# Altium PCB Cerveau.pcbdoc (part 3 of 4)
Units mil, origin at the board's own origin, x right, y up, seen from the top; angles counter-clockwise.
Board outline 3985.6 x 3546.5 mil, 2 copper layers (Top Layer, Bottom Layer), stack 62.2 mil thick; 170 components, 173 nets, 734 pads, 576 vias.
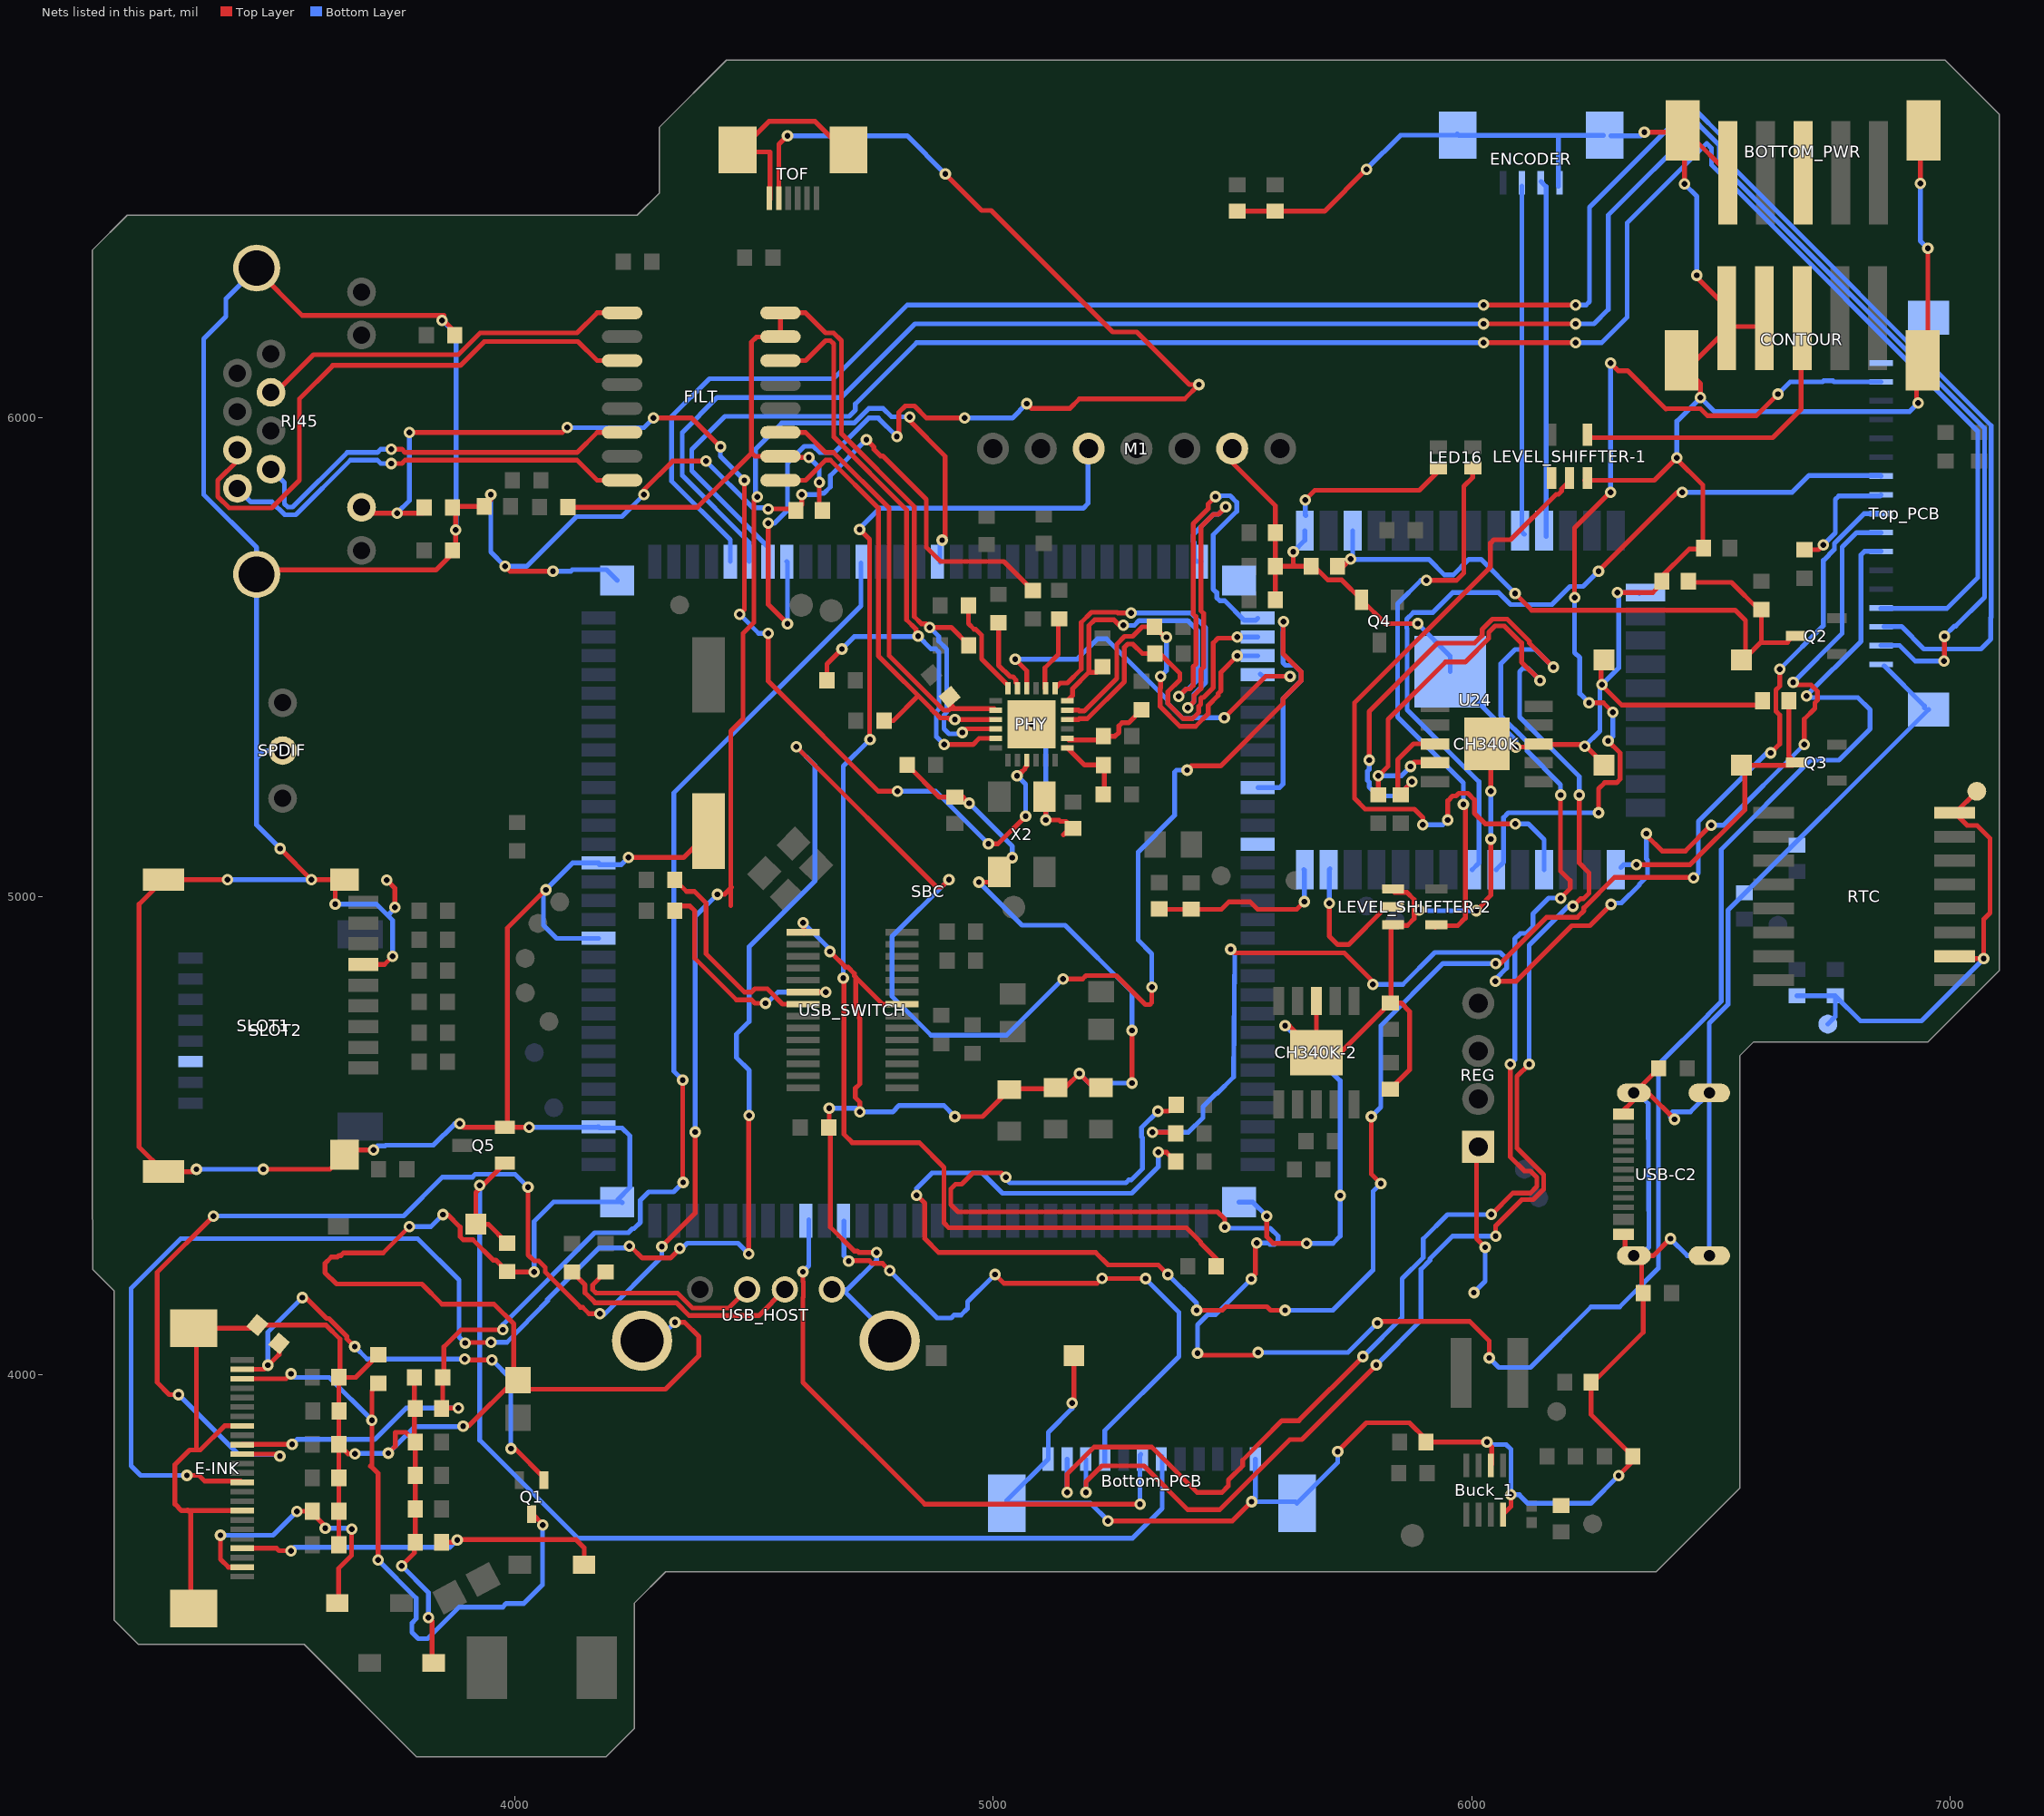
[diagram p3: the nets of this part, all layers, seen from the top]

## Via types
v1: diameter 24, hole 12, Top Layer to Bottom Layer, 576 vias

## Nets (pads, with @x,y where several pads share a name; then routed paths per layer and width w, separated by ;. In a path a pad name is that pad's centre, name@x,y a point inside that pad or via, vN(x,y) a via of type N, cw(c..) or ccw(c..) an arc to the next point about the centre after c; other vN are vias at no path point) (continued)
E-INK_D/C: E-INK.11 SBC.16 | length 4549
  Top Layer w10: v1(3297.7,3958.8) 3278.3,3958.8 3253,3984.2 3253,4214.4 v1(3370.7,4332.1) ; E-INK.11@3430.7,3834.5 3505.1,3834.5 v1(3509.3,3830.3) ; v1(4027.9,4392.5) 4027.9,4251 4040.6,4238.3 4050.2,4238.3 4063.7,4224.8 4063.7,4215.1 4137.6,4141.2 4142,4141.2 4155.3,4127.9 v1(4178.3,4127.9) ; v1(4307.4,4268.6) 4377,4338.2 v1(4377,4507.8) ; v1(4423.7,5004.5) 4438.6,5004.5 4451.5,5017.4 ; 4451.5,4980.7 4451.5,5017.4 ; 4453.5,5019.4 4451.5,5017.4 ; v1(4507.2,5835.3) 4500,5828.1 4500,5572.6 4477.3,5549.9 4477.3,5371.1 4451.5,5345.3 4451.5,5017.4 ; v1(4825.8,6002.4) 4825.8,5993.9 4899.4,5920.3 4899.4,5751 v1(4893.2,5744.8)
  Bottom Layer w10: v1(3297.7,3958.8) 3422.8,3833.7 v1@3509.9,3833.7 ; v1(3370.7,4332.1) 3767.8,4332.1 3849,4413.4 3911.5,4413.4 3917.5,4419.4 4000.9,4419.4 v1(4027.9,4392.5) ; v1@4180.2,4126.9 4187.5,4126.9 4307.7,4247.2 v1@4307.7,4267.1 ; v1(4377,4507.8) 4377,4957.8 v1(4423.7,5004.5) ; v1(4507.2,5835.3) 4503.1,5839.4 4503.1,5934.4 4558.3,5989.6 4709.6,5989.6 4740,6020 4770,6020 4787.6,6002.4 v1(4825.8,6002.4) ; SBC.16@4888.4,5699 4888.4,5740 v1(4893.2,5744.8)
E-INK_DIN: E-INK.14 SBC.40 | length 6237.3
  Top Layer w10: v1(3315,3790) 3340.2,3790 3351.9,3778.3 3427.9,3778.3 E-INK.14@3430.7,3775.5 ; v1(3896.4,4066.7) 3897.3,4067.6 v1@3948.2,4067.6 ; v1(4239.6,4269.3) 4241.7,4269.3 4266.6,4244.4 4325.3,4244.4 v1(4345.2,4264.3) ; v1(4489.2,4253) 4489.2,4541.5 v1(4490.1,4542.4) ; v1(4588.6,5312.9) 4881.9,5019.6 4891.9,5019.6 v1(4907.5,5035.1) ; v1(5145.8,4827.7) 5186.8,4827.7 5193.8,4834.7 5257.1,4834.7 5317.9,4774 5327.3,4774 5331.5,4778.2 v1(5331.5,4810.5) ; v1(5405.1,5264) 5414.1,5272.9 5475.3,5272.9 5605.5,5403.1 5605.5,5412.7 5643.5,5450.7 5643.5,5469.7 5605.5,5507.7 5605.5,5551.6 5606.4,5552.6 v1(5606.4,5574.6)
  Bottom Layer w10: v1@3316.2,3789.9 3218.6,3789.9 3198.3,3810.2 3198.3,4181.1 3302.1,4284.9 3797,4284.9 3883.6,4198.3 3883.6,4079.5 v1(3896.4,4066.7) ; v1(3950.8,4068.2) 3983.7,4068.2 4068.9,4154.9 ; 4068.4,4155.3 4068.4,4157.7 4177,4265.6 4240.6,4265.6 v1@4245.2,4270.3 ; v1(4345.2,4264.3) 4349.1,4264.3 4360.5,4275.6 4466.6,4275.6 v1(4489.2,4253) ; v1(4490.1,4542.4) 4490.1,4636.5 4463.5,4663.1 4463.5,4712.2 4490.1,4738.7 4490.1,4895.1 4627.2,5032.2 4627.2,5274.3 v1(4588.6,5312.9) ; v1(4907.5,5035.1) 4788.4,4916 4788.4,4791.6 4870,4710 5028.1,4710 v1(5145.8,4827.7) ; v1(5331.5,4810.5) 5331.5,4880.3 5302.7,4909.1 5302.7,5092.9 5379,5169.2 5379,5259.9 5383.1,5264 v1(5405.1,5264) ; SBC.40@5553,5227.6 5598.4,5227.6 5605.5,5234.6 5605.5,5412.7 5643.5,5450.7 5643.5,5469.7 5630,5483.2 5610.9,5483.2 5605.5,5488.7 5605.5,5573.6 v1(5606.4,5574.6)
E-INK_GDR: E-INK.2 Q1.1 R28.2 | length 1034.8
  Top Layer w10: E-INK.2@3430.7,4011.7 3476.7,4011.7 3507.7,4042.7 R28.2@3507.7,4065.9 ; v1(3556.2,4161.7) 3563.2,4161.7 3606.8,4118.1 3611.7,4118.1 3649,4080.8 3649,4075.9 v1(3665.7,4059.2) ; v1(3895.3,4033.2) 3897,4031.4 v1(3952.7,4031.4) ; v1(3992,3846) 4000.8,3846 Q1.1@4062.2,3784.6
  Bottom Layer w10: v1(3484.2,4020.4) 3484.2,4089.7 v1(3556.2,4161.7) ; v1(3665.7,4059.2) 3691.7,4033.2 v1(3895.3,4033.2) ; v1(3952.7,4031.4) 3992,3992.1 v1(3992,3846)
E-INK_PREGL: C24.1 E-INK.23 U23.2 | length 563.6
  Top Layer w10: v1(3385,3665) 3385,3615 3401.7,3598.3 E-INK.23@3430.7,3598.3 ; v1(3545,3715) C24.1@3577.4,3715 ; C24.1@3586,3702.1 3604.2,3683.9 v1(3604.2,3679.4) ; U23.2@3632.1,3527.9 3632.1,3595.6 3659.3,3622.7 3659.3,3677.7 v1(3659.7,3678)
  Bottom Layer w10: v1(3385,3665) 3495,3665 v1(3545,3715) ; v1(3604.2,3679.4) 3658.3,3679.4 v1(3659.7,3678)
E-INK_PREVGH: C22.1 E-INK.21 U21.1 | length 798.4
  Top Layer w10: E-INK.21@3430.7,3637.7 3502.3,3637.7 3507.5,3632.5 v1(3532.5,3632.5) ; C22.1@3847.6,3650 3875,3650 v1(3880,3655) ; v1@3883.8,3655.7 4128.5,3655.7 4145.6,3638.7 4145.6,3605.1 U21.1@4145.1,3604.6
  Bottom Layer w10: v1(3532.5,3632.5) 3540,3640 3865,3640 v1(3880,3655)
E-INK_RESE: E-INK.3 Q1.3 R27.1 | length 1367.7
  Top Layer w10: E-INK.3@3430.7,3992 3522,3992 v1(3532.5,4002.5) ; 3697.8,3809.2 3700,3811.4 ; 3699.6,3809.2 3714.7,3794.1 v1(3714.7,3613) ; 3701.6,3811.4 v1(3701.6,3905.5) 3701.6,3966.9 R27.1@3715,3980.3 ; Q1.3@4035.2,3711.3 4058.4,3688.1 v1(4058.4,3686.5)
  Bottom Layer w10: v1(3532.5,4002.5) 3540,3995 3612.1,3995 v1(3701.6,3905.5) ; v1(3714.7,3613) 3794.2,3533.4 3794.2,3490.3 3785.3,3481.3 3785.3,3462.3 3798.7,3448.8 3817.8,3448.8 3883.6,3514.6 3975,3514.6 3982.7,3522.4 4019.5,3522.4 4058.4,3561.3 v1(4058.4,3686.5)
E-INK_RST: C15.2 E-INK.10 R54.2 SBC.12 | length 2793.2
  Top Layer w10: E-INK.10@3430.7,3854.2 3431.5,3855 v1(3535,3855) ; C15.2@3847.6,3930 C15.2@3848.6,3931 ; R54.2@3849.7,3995 3849.7,3932.1 C15.2@3848.6,3931 ; R54.2@3852.7,3991.8 3852.1,3992.5 3852.1,4058.6 3888,4094.5 v1(3975.3,4094.5) ; v1(3882.6,3931) C15.2@3848.6,3931 ; v1@4350,4400.1 4351.2,4401.4 v1(4351.2,4616.4)
  Bottom Layer w10: v1(3535,3855) 3545.2,3865.2 3707.3,3865.2 3772.8,3930.7 v1@3882.6,3930.7 ; v1(3975.3,4094.5) 3975.3,4105.1 4167.3,4297.1 4237.6,4297.1 4246.1,4305.6 4249.3,4305.6 4262.7,4319 4262.7,4365.4 4279.9,4382.6 4332.2,4382.6 v1(4352.1,4402.4) ; v1(4351.2,4616.4) 4332.7,4634.9 4332.7,5216.4 4723.5,5607.3 SBC.12@4723.5,5697.1
EN_1: C12.1 C13.1 ESP_RST.1 Q2.3 R21.1 U24.3 | length 1438.5
  Top Layer w10: C12.1@5719.8,5690.3 5732.2,5690.3 v1(5747.2,5705.3) ; v1(6090.5,5633.3) 6125.3,5598.5 6550.5,5598.5 6572.1,5576.9 ESP_RST.1@6572.1,5498.7 ; C13.1@6457.8,5656.5 6542.8,5656.5 R21.1@6601.1,5598.2 ; ESP_RST.1@6572.1,5492 ESP_RST.1@6572.1,5498.7 ; R21.1@6604.5,5598.2 R21.1@6605.2,5598.2 ; R21.1@6605.2,5601 R21.1@6605.2,5598.2 ; 6659,5531.4 Q2.3@6672.7,5545.1 ; 6660,5530.3 6603.8,5530.3 ; ESP_RST.1@6572.1,5498.7 6603.8,5530.3 ; 6603.8,5530.3 6605.2,5531.7 R21.1@6605.2,5598.2
  Bottom Layer w10: v1@5747,5704.6 5910.4,5704.6 5942.7,5672.3 5961.8,5672.3 5994,5704.6 6019.2,5704.6 v1(6090.5,5633.3) ; v1@5751.1,5709.2 U24.3@5751.1,5764.6
ENC_A: ENCODER.3 U24.11 | length 746.6
  Bottom Layer w10: ENCODER.3@6144.6,6494.4 6155.5,6483.5 U24.11@6155.5,5752.3
ENC_B: ENCODER.2 U24.10 | length 729.4
  Bottom Layer w10: ENCODER.2@6104.8,6484.5 6104.8,5762.2 U24.10@6109.8,5757.2
ETH_ACT: PHY.3 R26.1 RJ45.11 | length 2399.2
  Top Layer w10: RJ45.11@3686.9,5801.4 v1(3754.1,5801.4) 3806.7,5801.4 R26.1@3817.7,5812.4 ; v1(3780,5970) 4100,5970 v1(4110,5980) ; v1(4290,6000) 4370,6000 v1(4430,5940) ; v1(4470,5590) 4480,5600 v1(4480,5870) ; v1(4530,5550) 4530,5450 4760,5220 v1(4800,5220) ; v1(4990,5110) 5010,5110 v1(5067.7,5167.7) ; v1(5049.7,5252.4) 5058.1,5260.8 5060.5,5260.8 5067,5267.3 5067,5269.7 5070.2,5272.9 PHY.3@5070.2,5284.9
  Bottom Layer w10: v1(3754.1,5801.4) 3780,5827.3 v1(3780,5970) ; v1(4110,5980) 4270,5980 v1(4290,6000) ; v1(4430,5940) 4430,5920 v1(4480,5870) ; v1(4470,5590) 4510,5550 v1(4530,5550) ; v1(4800,5220) 4880,5220 v1(4990,5110) v1@4998.8,5110 ; v1(5049.7,5252.4) 5067.7,5234.4 v1(5067.7,5167.7)
ETH_RX+: FILT.11 RJ45.3 | length 1229.5
  Top Layer w10: RJ45.3@3420.6,5933.2 3420.6,5910.8 3379.6,5869.9 3379.6,5835.9 3403.6,5811.9 3491.9,5811.9 3550,5870 3550,6040 3620,6110 3886.6,6110 3936.6,6160 4132.3,6160 4172.3,6120 FILT.11@4224.5,6120
ETH_RX-: FILT.9 RJ45.6 | length 802.8
  Top Layer w10: RJ45.6@3490.6,6053.7 3500.6,6053.7 3579.3,6132.4 3882.3,6132.4 3927.9,6178 4130.3,6178 4172.3,6220 FILT.9@4224.5,6220
ETH_TX+: FILT.16 RJ45.1 | length 897.1
  Top Layer w10: v1(3742.3,5905) 3764.3,5905 3771.3,5912 4130.3,5912 4172.3,5870 FILT.16@4224.5,5870
  Bottom Layer w10: RJ45.1@3420.6,5852.9 3448.8,5824.6 3492.6,5824.6 3519.4,5797.9 3542.6,5797.9 3656.7,5912 3713.3,5912 3720.3,5905 v1(3742.3,5905)
ETH_TX-: FILT.14 RJ45.2 | length 862.8
  Top Layer w10: v1(3742.3,5935) 3764.3,5935 3771.3,5928 4130.3,5928 4172.3,5970 FILT.14@4224.5,5970
  Bottom Layer w10: RJ45.2@3490.6,5893 3518.9,5864.8 3518.9,5820.9 3526,5813.9 3536,5813.9 3650.1,5928 3713.3,5928 3720.3,5935 v1(3742.3,5935)
GND: Bottom_PCB.1 Bottom_PCB.12 Bottom_PCB.13 Bottom_PCB.14 BOTTOM_PWR.1 BOTTOM_PWR.3 BOTTOM_PWR.6 BOTTOM_PWR.7 Buck_1.4 Buck_1.6 BUZZER.2 C1.1 C2.2 C3.2 C4.1 C5.1 C6.2 C7.2 C8.1 C9.2 C10.1 C11.2 C12.2 C13.2 C14.1 C15.1 C16.1 C17.1 C18.1 C19.2 C20.2 C21.2 C22.2 C23.2 C24.2 C25.2 C26.1 C27.1 C28.2 C29.1 C30.2 C31.2 C33.1 C34.2 C35.2 C36.1 C37.2 CH340K-2.3 CH340K-2.11 CH340K.3 CH340K.11 CONTOUR.4 CONTOUR.5 CONTOUR.6 CONTOUR.7 E-INK.8 E-INK.17 E-INK.25 E-INK.26 ENCODER.4 ENCODER.5 ENCODER.6 ESP_BOOT.1 ESP_RST.2 GND.1 LED16.2 LEVEL_SHIFFTER-1.1 LEVEL_SHIFFTER-1.3 LEVEL_SHIFFTER-2.1 LEVEL_SHIFFTER-2.3 M1.6 pad.GND PHY.25 PORT-1.2 PORT-2.2 PORT-3.1 Q4.2 Q5.2 R1.1 R2.1 R7.1 R8.2 R19.1 R23.2 R24.1 R25.2 R26.2 R27.2 R28.1 R31.2 R54.1 REG.1 RJ45.13 RJ45.14 RST_CMPT.2 RTC.2 RTC.8 SBC.93 SBC.103 SBC.107 SBC.121 SBC.122 SBC.123 SBC.124 SLOT1.6 SLOT1.10 SLOT1.11 SLOT1.12 SLOT1.13 SLOT2.6 SPDIF.2 TOF.6 TOF.7 TOF.8 Top_PCB.1 Top_PCB.17 Top_PCB.18 Top_PCB.19 U22.1 U24.1 U24.15 U24.38 U24.39 USB-C2.A1B12 USB-C2.B1A12 USB-C2.EH1 USB_HOST.4 USB_HOST.5 USB_SWITCH.1 USB_SWITCH.22 X2.2 X2.4 | length 32420.4
  Top Layer w10: 3316.6,3717.9 3318,3716.4 ; E-INK.25@3323.2,3510.6 3323.2,3711.2 3318,3716.4 ; v1(3335,4430) 3329.9,4424.9 SLOT1.12@3266.3,4424.9 3215,4476.2 3215,4983.8 SLOT1.11@3266.3,5035.1 v1(3400,5035.1) ; E-INK.17@3430.7,3716.4 3318,3716.4 ; E-INK.8@3430.7,3893.6 3393.6,3893.6 3343,3843 3334.9,3843 ; RJ45.13@3449.7,5682.4 3835.1,5682.4 R25.2@3868.4,5715.7 ; RJ45.14@3460.2,6310.4 3556.3,6214.3 3663,6214.3 3697,6214.3 3697.1,6214.3 v1@3852.2,6214.3 ; v1(3475,4430) 3614,4430 SLOT1.13@3644.3,4460.3 3654,4470 v1(3705,4470) ; v1(3510,5100) 3574.9,5035.1 v1(3575,5035.1) SLOT1.10@3644.3,5035.1 3625,5015.8 v1(3625,4984.1) ; C25.2@3632.6,3645 C24.2@3632.6,3715 C23.2@3632.6,3785 C19.2@3632.6,3855 C16.1@3632.6,3995 3667.9,3995 R27.2@3715,4042.1 ; C19.2@3633.7,3853.4 3651.8,3835.3 v1(3665.9,3835.3) ; C16.1@3635,3997.4 3635,4075 3605.9,4104.1 R28.1@3462.3,4104.1 3456.1,4097.9 E-INK.26@3329.3,4097.9 3334.9,4092.3 3334.9,3843 ; SLOT1.6@3683.7,4857.9 3727.9,4857.9 v1(3745,4875) ; v1(3732.8,5034.4) 3749.5,5017.6 v1(3749.5,4977.4) ; v1(3735.9,3836.5) 3750.5,3851.1 3750.5,3880 3772.4,3880 C18.1@3790.3,3862.1 ; v1(3763.8,3601.2) 3790.5,3627.8 C22.2@3790.5,3649.4 ; v1(3780,4310) 3725,4255 3642.1,4255 3636.6,4249.5 3632.7,4249.5 3629.7,4246.5 3617,4246.5 3603.5,4233.1 3603.5,4214 3627.6,4190 3806.2,4190 3848.2,4148 3956.8,4148 3998.2,4106.6 3998.2,3997.9 C33.1@4006.9,3989.3 4026.2,3970 4315,3970 4385,4040 4385,4080 4355,4110 v1(4335,4110) ; R54.1@3790.3,3995 C18.1@3790.3,3862.1 ; C22.2@3792.4,3650 C21.2@3792.4,3720 C20.2@3792.4,3790 C18.1@3792.4,3860 C18.1@3790.3,3862.1 ; v1(3819.6,3493.1) 3827.3,3485.4 U22.1@3827.3,3405.2 ; v1(3848.4,6204.1) 3851.2,6204.1 R24.1@3877.9,6177.5 ; v1(3850,4335) 3860,4335 3886.1,4308.9 3886.1,4288.8 3892.5,4282.4 3912.6,4282.4 3955,4240 3960.7,4240 R23.2@3984.6,4216 ; R25.2@3873.2,5721.7 3876.7,5725.3 R26.2@3876.7,5811 ; R26.2@3873.5,5815.3 C26.1@3932.9,5815.3 ; v1(3885,4525) 3892.6,4517.4 Q5.2@3979.7,4517.4 v1(4030,4517.4) ; v1(3892.2,3893.2) 3903.7,3893.2 C33.1@4000.8,3990.4 ; C26.1@3936.4,5815.5 3950,5829 v1(3950,5840) ; Q5.2@3979.5,4519.2 3984.8,4524.5 3984.8,4934.4 v1@4066.2,5015.9 ; v1(3980,5690) 3990,5680 v1(4080,5680) ; R23.2@3989.6,4223.4 3997.7,4215.3 v1(4040.7,4215.3) ; v1(4237.8,5081.5) 4353,5081.5 BUZZER.2@4391.8,5120.2 ; v1(4270,5840) 4270,5850 4330,5910 v1(4400,5910) ; TOF.7@4469.5,6556.4 4533.5,6556.4 TOF.6@4533.5,6457.2 ; TOF.7@4469.5,6558.4 4531.1,6620 4627.9,6620 TOF.8@4687.7,6560.2 ; v1(4530,5810) 4585,5810 C27.1@4587.8,5807.1 4600,5819.3 v1(4600,5840) ; v1(4603.1,4945.1) 4604,4944.2 USB_SWITCH.1@4604,4923 ; v1(4657.2,4557.6) 4657.2,4521.2 R19.1@4663.8,4514.6 ; v1(4658.7,4884.8) 4691.1,4852.4 4696.4,4852.4 4709.8,4838.9 4709.8,4833.7 4712.8,4830.7 ; R19.1@4659.6,4510.7 4659.6,4309 4709.6,4259 4715.8,4259 4718.8,4256 v1(4756.3,4256) ; 4712.8,4763.2 4719.8,4756.3 4719.8,4746.1 4721.5,4744.4 ; 4712.8,4763.3 4712.8,4830.7 ; 4712.8,4832 4712.8,4830.7 ; v1(4721.4,4549.7) 4721.4,4570.2 4711.7,4579.9 4711.7,4598.9 4721.4,4608.7 4721.4,4744.4 ; v1(4735,5955) 4750.8,5939.2 4750.8,5934.3 4764.3,5920.8 4769.2,5920.8 4860,5830 4860,5730 4890,5700 5022.4,5700 R8.2@5082.9,5639.5 ; USB_SWITCH.22@4806.4,4774.9 4768.7,4774.9 4712.8,4830.7 ; R7.1@4820.3,5275 4887.8,5207.6 C5.1@4920,5207.6 4937.4,5207.6 v1(4950,5195) ; v1(4920,4540) 4977.4,4540 PORT-1.2@5033.5,4596.1 ; v1(4970,5030) 4991.5,5030 X2.4@5012.8,5051.3 ; PORT-1.2@5043,4598.3 PORT-3.1@5130.5,4598.3 ; X2.2@5107.2,5208.7 5110,5206 v1(5110,5160) 5137.5,5160 5140.5,5157 5152.1,5157 C6.2@5166.7,5142.4 ; PORT-3.1@5130.5,4600.4 5150.4,4600.4 v1(5180,4630) 5209.6,4600.4 PORT-2.2@5225.5,4600.4 ; 5146.4,5128.8 C6.2@5152.6,5135.1 ; C6.2@5153,5135.4 C6.2@5162.9,5145.3 ; C6.2@5153.4,5134.3 C6.2@5153.4,5135 ; v1(5165,3941) 5168.7,3944.7 RST_CMPT.2@5168.7,4040 ; v1(5240,3695) 5500,3695 v1(5540,3735) ; v1(5290,4610) v1(5290,4720) ; C3.2@5347.2,4972.8 5476.8,4973.2 5492.4,4988.8 5537.1,4988.8 5552.7,4973.2 5634.2,4973.2 v1(5650.3,4989.3) ; M1.6@5501.4,5935.7 5501.4,5905.1 5589.7,5816.8 C11.2@5589.7,5763.8 ; C7.2@5510,6432.4 5589,6432.4 C8.1@5589.2,6432.3 5692.3,6432.3 v1(5780,6520) ; v1(5571.5,4332) 5571.5,4288.5 5585,4275 v1(5655,4275) ; C9.2@5589.8,5620.3 C10.1@5589.8,5690.3 ; C11.2@5589.8,5760.3 C10.1@5589.8,5690.3 ; v1(5610,4730) 5619,4730 CH340K-2.11@5675.4,4673.6 ; v1(5627.2,5720.3) 5627.2,5694.2 5631.1,5690.3 ; v1(5652.2,5828.9) 5672.2,5848.9 5890.7,5848.9 LED16.2@5936.2,5894.4 ; CH340K-2.3@5675.4,4781.9 CH340K-2.11@5675.4,4673.6 ; v1(5720,3840) 5780,3900 5870,3900 5904.5,3865.5 C31.2@5904.5,3859.6 v1(6031.9,3859.6) 6041.9,3849.6 6041.9,3813 Buck_1.6@6039.7,3810.8 ; C1.1@5830,4597.4 5870,4637.4 5870,4760 5852.4,4777.6 C2.2@5831.5,4777.6 ; LEVEL_SHIFFTER-2.3@5838.3,4943.7 5831.5,4937 C2.2@5831.5,4777.6 ; LEVEL_SHIFFTER-2.1@5838.9,5008.4 5864.8,5008.4 5879.7,4993.5 5879.7,4961 ; LEVEL_SHIFFTER-2.3@5839.2,4939.5 5865.4,4939.5 5879.7,4953.9 5879.7,4961 ; v1(5887.2,5570.3) 5819.6,5570.3 Q4.2@5769.8,5620 5728.3,5661.6 5699.5,5661.6 5670.8,5690.3 C12.2@5664.7,5690.3 5631.1,5690.3 ; v1(5890.2,4971.5) 5879.7,4961 ; v1(6009.8,4970.2) 6030.3,4990.6 6030.3,4992.7 6040,5002.4 v1(6040,5120) ; REG.1@6013.1,4476.9 REG.1@6013.6,4476.9 ; REG.1@6018.2,4477.4 6010,4469.2 6010,4285.1 v1(6028.1,4267) ; CH340K.11@6031.7,5318.8 CH340K.11@6038.2,5312.3 ; v1(6040,5220) 6040,5310.5 CH340K.11@6038.2,5312.3 ; Buck_1.4@6065.3,3708.4 6081.9,3725 v1(6081.9,3749.6) ; CH340K.3@6140.1,5317.1 6135.3,5312.3 v1(6092.1,5312.3) CH340K.11@6038.2,5312.3 ; CH340K.3@6154,5317.5 v1@6232.2,5317.5 ; LEVEL_SHIFFTER-1.3@6236.1,5870 6381.7,5870 v1@6427.3,5915.6 ; v1@6238.5,5314.4 ESP_BOOT.1@6281.5,5271.5 ; C30.2@6249.5,3984.6 6249.5,3917 6336.6,3829.9 R31.2@6336.6,3829.6 6336.6,3819.2 v1(6306.9,3789.6) ; C30.2@6255,3985.8 6358.3,4089.1 R2.1@6358.3,4164.6 ; v1@6270.1,5441.3 ESP_RST.2@6270.1,5500.9 ; v1@6272.2,5441.3 6313.3,5400.1 C14.1@6607.4,5400.1 ; v1(6304.4,5635.3) 6378.4,5635.3 C13.2@6403.8,5660.7 ; USB-C2.B1A12@6311.7,4547.5 6337.5,4573.3 USB-C2.EH1@6337.5,4585.2 ; USB-C2.A1B12@6320.6,4292.4 6320.6,4267 USB-C2.EH1@6340.8,4246.8 ; USB-C2.EH1@6338.9,4249.4 6379.4,4249.4 v1(6415,4285) ; USB-C2.EH1@6338.9,4589.5 USB-C2.EH1@6339.5,4589.5 ; USB-C2.EH1@6341.7,4244.7 6355,4231.4 R2.1@6355,4174.7 ; v1(6360.7,6597.5) BOTTOM_PWR.6@6439.7,6597.5 ; R1.1@6390.8,4640.9 USB-C2.EH1@6339.5,4589.5 ; C13.2@6392.3,5663.9 6454.7,5726.3 C28.2@6484.9,5726.3 ; v1(6424.1,4534.1) 6368.8,4589.5 USB-C2.EH1@6339.5,4589.5 ; v1@6424.5,5918.5 v1@6427.3,5915.6 ; v1(6444.7,6489.2) BOTTOM_PWR.6@6444.7,6594.5 ; BOTTOM_PWR.6@6453.1,6594.5 BOTTOM_PWR.1@6541,6506.6 ; v1(6470.5,6298.5) 6470.5,6293.5 CONTOUR.5@6536.1,6227.9 ; v1(6478,6042.7) 6478,6071.9 6445.9,6104 6451.6,6104 6538.7,6191.1 6608.6,6191.1 CONTOUR.4@6612.9,6186.8 ; C28.2@6483,5733 6483,5860 v1@6427.3,5915.6 ; CONTOUR.6@6929.7,6116.9 6929.7,6034.1 v1(6932.6,6031.3) ; v1(6937.4,6490.2) 6937.4,6538.9 BOTTOM_PWR.7@6953.3,6554.8 ; v1(6953.2,6354.6) 6953.3,6354.5 CONTOUR.6@6953.3,6105.7 ; RTC.2@7009,4875 7014,4870 v1(7070,4870) 7070,4952.5 7083,4965.5 7083,5121.5 7056,5148.5 7035.5,5148.5 RTC.8@7009,5175 7010.5,5175 GND.1@7055.5,5219.9 ; 3318,3716.4 3303.6,3716.4 3290,3730 3290,3812.5 3320.5,3843 3334.9,3843 ; C10.1@5589.8,5690.3 5631.1,5690.3 ; CH340K-2.11@5675.4,4673.6 5726,4673.6 C2.2@5830,4777.6 C2.2@5831.5,4777.6
  Bottom Layer w10: v1(3335,4430) v1(3475,4430) ; v1(3400,5035.1) v1(3575,5035.1) ; RJ45.14@3460.7,6313.5 3396.5,6249.3 3396.5,6212 3350,6165.5 3350,5840 3460.7,5729.3 RJ45.13@3460.7,5673.4 3460.7,5290 ; v1(3510,5100) 3460.7,5149.3 3460.7,5290 ; SPDIF.2@3515,5305 3475.7,5305 3460.7,5290 ; v1(3625,4984.1) 3710.9,4984.1 3745,4950 v1(3745,4875) ; v1@3665.9,3836.2 v1@3737.5,3836.2 ; v1(3705,4470) 3713.7,4478.7 3728.8,4478.7 3730.1,4480 3830,4480 3875,4525 v1(3885,4525) ; v1(3735.9,3836.5) 3791.1,3891.7 v1@3888.8,3891.7 ; 3738.1,4963.3 3749.5,4974.7 v1(3749.5,4977.4) ; v1(3763.8,3601.2) 3819.6,3545.5 v1(3819.6,3493.1) ; v1(3780,4310) 3825,4310 v1(3850,4335) ; v1(3848.4,6204.1) 3877.7,6174.8 3877.7,5766.7 v1(3876.9,5765.9) ; v1(3950,5840) 3950,5720 v1(3980,5690) 4025.2,5690 4129.2,5794 4224,5794 v1(4270,5840) ; v1(4030,4517.4) SBC.93@4173.5,4517.4 ; v1(4040.7,4215.3) 4040.7,4321 4081.4,4361.6 4223.1,4361.6 SBC.124@4224.3,4360.5 ; v1(4080,5680) 4117.5,5680 4120.5,5683 4192,5683 SBC.123@4214.4,5660.6 ; SBC.93@4174.5,4518.4 SBC.93@4175,4518.9 ; SBC.103@4175,4912.6 4087.4,4912.6 4060,4940 4060,5009 v1(4065,5014) 4121.1,5070.1 SBC.107@4175,5070.1 ; SBC.93@4176.7,4516.2 4224.3,4516.2 4240.6,4499.9 4240.6,4391.9 SBC.124@4216.2,4367.5 ; SBC.107@4177.2,5066.6 4222.9,5066.6 v1(4237.8,5081.5) ; USB_HOST.5@4266.3,4071.5 4296.5,4071.5 v1(4335,4110) ; v1(4400,5910) 4497.7,5812.3 4527.7,5812.3 v1(4530,5810) ; v1(4600,5840) 4634.4,5840 4637.1,5842.7 4646.1,5842.7 4659.6,5856.2 4659.6,5879.6 v1(4735,5955) ; v1(4603.1,4945.1) 4658.7,4889.4 v1(4658.7,4884.8) ; v1(4657.2,4557.6) 4713.5,4557.6 v1(4721.4,4549.7) 4790,4549.7 4803.6,4563.3 4896.7,4563.3 v1(4920,4540) ; USB_HOST.4@4664.1,4178.5 USB_HOST.4@4685.3,4178.5 ; v1(4756.3,4256) 4756.3,4239.4 4695.4,4178.5 USB_HOST.4@4685.3,4178.5 ; USB_HOST.5@4786.7,4077.1 USB_HOST.4@4685.3,4178.5 ; v1(4950,5195) 5040,5105 v1(5040,5081.1) ; v1(4970,5030) 5060,4940 5150,4940 5290,4800 v1(5290,4720) ; v1(5080,5360) 5110,5330 v1(5110,5160) ; v1(5165,3941) 5165,3930 5115,3880 Bottom_PCB.12@5115,3824.3 5028.4,3737.7 Bottom_PCB.13@5028.4,3731.8 5203.2,3731.8 v1(5240,3695) ; v1(5180,4630) 5200,4610 v1(5290,4610) ; SBC.122@5513.6,4361.4 5542,4361.4 v1(5571.5,4332) ; Bottom_PCB.1@5548.1,3824.3 5548.1,3743.1 v1(5540,3735) 5631.5,3735 Bottom_PCB.14@5634.7,3731.8 5720,3817.1 v1(5720,3840) ; v1(5610,4730) 5725,4615 v1(5725,4375) 5725,4290 5710,4275 v1(5655,4275) ; v1(5627.2,5720.3) 5651.1,5744.2 U24.1@5651.1,5764.6 ; U24.38@5649,5056.5 5650.3,5055.2 v1(5650.3,4989.3) ; v1(5652.2,5828.9) 5652.2,5797.4 U24.1@5653.1,5796.6 ; v1(5780,6520) 5851.4,6591.4 ENCODER.6@5970.9,6591.4 ; v1(5887.2,5570.3) 5955.2,5502.3 U24.39@5955.2,5469.7 ; v1(5890.2,4971.5) 5891.6,4970.2 v1(6009.8,4970.2) ; ENCODER.6@5969.9,6594.3 ENCODER.6@5971.9,6592.4 ; ENCODER.6@5973.3,6590.9 ENCODER.5@6275.3,6590.9 ; v1(6004.5,4172.2) 6028.1,4195.8 v1(6028.1,4267) ; U24.39@6009.8,5408.9 6092.1,5326.7 v1(6092.1,5312.3) ; v1(6031.9,3859.6) 6036.9,3854.6 6071.9,3854.6 6081.9,3844.6 v1(6081.9,3749.6) 6099.4,3749.6 6117.4,3731.6 6248.9,3731.6 v1(6306.9,3789.6) ; v1(6040,5120) v1(6040,5220) ; ENCODER.4@6181,6484.8 6181,6590.1 ; v1(6235.9,5313.9) 6268,5345.9 6268,5437.8 6272.8,5443.3 6307.1,5477.6 v1@6307.1,5634.6 ; ENCODER.5@6290.7,6590.1 6353.3,6590.1 v1(6360.7,6597.5) ; v1(6304.4,5635.3) 6348.3,5635.3 U24.15@6350.3,5633.3 ; USB-C2.EH1@6350.3,4246.8 6370.3,4266.8 6368.9,4566.9 6354.8,4581 USB-C2.EH1@6351.3,4581 ; v1(6415,4285) 6450.6,4249.4 USB-C2.EH1@6496.4,4249.4 USB-C2.EH1@6496.4,4589.5 ; v1(6424.1,4534.1) 6420,4534.1 6415.4,4538.8 6415.4,4545.4 6420,4550 6456.9,4550 USB-C2.EH1@6496.4,4589.5 ; v1(6428.8,5917.1) 6428.8,5993.4 v1(6478,6042.7) 6507,6013.7 6915.1,6013.7 v1(6932.6,6031.3) ; v1(6444.7,6489.2) 6470.5,6463.4 v1(6470.5,6298.5) ; C36.1@6680,4792.4 C35.2@6760,4792.4 ; pad.GND@6744.2,4733.3 6760,4749.1 C35.2@6760,4792.4 ; Top_PCB.1@6862,5482.3 6946.2,5398.1 Top_PCB.19@6946.2,5394.2 ; v1(6937.4,6490.2) 6937.4,6370.4 v1(6953.2,6354.6) ; Top_PCB.19@6954.7,5390.6 6535.5,4971.4 6535.5,4774.3 6496.4,4735.2 USB-C2.EH1@6496.4,4589.5 ; v1(7070,4870) 6940,4740 6812.4,4740 C35.2@6760,4792.4
  other v1: 6272.2,5442.7
GP1: SBC.8 TOF.5 | length 2748.4
  Top Layer w10: v1(4530,5780) 4530,5610 v1(4570,5570) ; TOF.5@4552,6459.1 4552,6572 v1(4570,6590) ; v1(4798.7,5961.3) 4802.8,5965.3 4802.8,6011.9 4816.3,6025.4 4835.3,6025.4 4860.7,6000 v1(4940,6000) ; v1(4900,6510) 4976,6434 4995.8,6434 5249.8,6180 5300,6180 5410,6070 v1(5430,6070) 5400,6040 5180,6040 5160,6020 5080,6020 v1(5070,6030)
  Bottom Layer w10: v1(4530,5780) 4542.5,5780 4570,5807.5 4570,5905.8 4605.2,5941 4624.3,5941 4637.8,5927.5 4667.5,5927.5 4740,6000 4760,6000 v1(4798.7,5961.3) ; SBC.8@4568.7,5700 4570,5698.7 v1(4570,5570) ; v1(4570,6590) 4820,6590 v1(4900,6510) ; v1(4940,6000) 5040,6000 v1(5070,6030)
HOST_D+: R44.2 USB_HOST.3 | length 514.8
  Top Layer w10: R44.2@4120,4215.3 4147,4188.3 4147,4171.7 4167.8,4150.9 4338,4150.9 4364.9,4124 4510.2,4124 USB_HOST.3@4564.7,4178.5
HOST_D-: R43.2 USB_HOST.2 | length 402.9
  Top Layer w10: R43.2@4190,4215.3 4163,4188.3 4163,4178.3 4170.1,4171.3 4340.2,4171.3 4371.5,4140 4447.4,4140 USB_HOST.2@4485.9,4178.5
I2S: M1.3 R55.2 | length 2883.5
  Top Layer w10: v1@4687.6,4830.3 4688,4829.9 4688,4502.8 4705.3,4485.5 4845.4,4485.5 4897.2,4433.7 4897.2,4317.8 4907.2,4307.8 5403.8,4307.8 5433.8,4277.8 5433.8,4275.7 5468.9,4240.6 R55.2@5468.9,4226.6 ; v1(4720.7,5767.3) 4741.6,5746.4 4741.6,5328.4 v1@4743.1,5326.8
  Bottom Layer w10: v1(4686.8,4829.4) 4686.8,5272.5 v1(4742.5,5328.1) ; v1@4720.6,5769.3 4762.7,5811.4 5188.2,5811.4 5198.2,5821.4 5198.2,5932.2 M1.3@5199.3,5933.4
INT_ACCEL: SBC.5 Top_PCB.3 | length 4493.7
  Top Layer w10: v1(6024.6,6236.3) v1(6217,6236.3)
  Bottom Layer w10: SBC.5@4450.6,5700 4450.6,5745.4 4327.7,5868.4 4327.7,6003 4407,6082.3 4666.4,6082.3 4820.4,6236.3 v1(6024.6,6236.3) ; v1(6217,6236.3) 6239,6236.3 6246.1,6243.4 6246.1,6440.4 6458.4,6652.7 6533.7,6577.5 6533.7,6536.2 7085.6,5984.2 7085.6,5583.9 ; Top_PCB.3@6861.6,5564.4 6898,5564.4 6944.9,5517.4 7064.2,5517.4 7084.8,5538 7084.8,5582.8
INT_EXT: SBC.7 Top_PCB.4 | length 4180.1
  Top Layer w10: v1(6024.6,6157.5) v1(6217,6157.5)
  Bottom Layer w10: SBC.7@4529.3,5700 4529.3,5730.7 4370,5890 4370,5934 4439.6,6003.6 4699,6003.6 4712,6016.6 4712,6029.5 4840,6157.5 v1(6024.6,6157.5) ; v1(6217,6157.5) 6271.6,6157.5 6324.8,6210.7 6324.8,6407.8 6491.1,6574 6501.1,6564 6501.1,6529.2 7057.6,5972.6 7057.6,5666.6 6993.1,5602.1 Top_PCB.4@6855.4,5602.1
INT_LUM: SBC.6 Top_PCB.2 | length 4383.7
  Top Layer w10: v1(6024.6,6196.9) v1(6217,6196.9) ; v1(6986.6,5492) 6987.9,5493.3 v1(6987.9,5543.7)
  Bottom Layer w10: SBC.6@4490,5700 4490,5740 4350,5880 4350,5969.7 4423.3,6043 4682.7,6043 4836.7,6196.9 v1(6024.6,6196.9) ; v1(6217,6196.9) 6255.3,6196.9 6285.5,6227 6285.5,6424.1 6474.8,6613.4 6517.4,6570.7 6517.4,6532.7 7071.6,5978.4 7071.6,5625.5 7011.3,5565.2 ; Top_PCB.2@6854.5,5524.9 6894,5524.9 6926.9,5492 v1(6986.6,5492) ; v1(6987.9,5543.7) 6987.9,5544.2 7009.4,5565.7
IO0_1: C14.2 ESP_BOOT.2 Q3.3 U24.25 | length 646.9
  Top Layer w10: v1(6344.5,5066.6) 6456.7,5066.6 6570.7,5180.6 ESP_BOOT.2@6570.7,5268.2 ; ESP_BOOT.2@6563.7,5274.3 6670.9,5274.3 Q3.3@6676.6,5280 6662.5,5294.1 C14.2@6662.5,5409.3
  Bottom Layer w10: U24.25@6311.6,5060.4 6317.8,5066.6 v1(6344.5,5066.6)
LED: Top_PCB.11 U24.31 | length 1728.4
  Top Layer w10: v1(6265,5680) 6430,5845 v1(6440,5845)
  Bottom Layer w10: U24.31@6001.1,5056 6015,5069.8 6015,5240 5865,5390 5865,5560 5864.2,5560.8 5864.2,5579.8 5877.7,5593.3 5918.3,5593.3 5960,5635 6056.2,5635 6081,5610.3 6167.7,5610.3 6205.5,5648 6233,5648 v1(6265,5680) ; v1(6440,5845) 6670,5845 6705,5880 6854,5880 Top_PCB.11@6855.3,5878.7
LED2: Top_PCB.16 U24.30 | length 2029.9
  Top Layer w10: v1(6215,5625) 6215,5770 v1(6290,5845) ; v1(6245,5405) 6275,5405 v1(6295,5385) ; v1(6265,5175) 6265,5225 6277.9,5237.9 6302.9,5237.9 6310,5245 6310,5300 v1(6285,5325) ; v1(6290,6115) 6306,6099 6325.8,6099 6405.8,6019 6477.8,6019.7 6492.5,6005 6595,6005 v1(6640,6050)
  Bottom Layer w10: U24.30@6051.1,5056 6066.6,5071.5 6066.6,5165 6076.6,5175 v1(6265,5175) ; v1(6215,5625) 6215,5509.8 6225.9,5498.9 6225.9,5424.1 v1(6245,5405) ; v1(6285,5325) 6295,5335 v1(6295,5385) ; v1(6290,5845) v1(6290,6115) ; v1(6640,6050) 6665.6,6075.6 6733.1,6075.6 6735.5,6078 6754.5,6078 6756.9,6075.6 Top_PCB.16@6855.3,6075.6
LED3: CONTOUR.3 LEVEL_SHIFFTER-1.4 | length 636.5
  Top Layer w10: LEVEL_SHIFFTER-1.4@6246.1,5964.2 6251.2,5959 6629,5959 6688.5,6018.5 6688.5,6179.7 CONTOUR.3@6684.2,6184
LED3-IN: LEVEL_SHIFFTER-1.2 U24.28 | length 1474
  Top Layer w10: v1(5898,5150) 5898,5164.8 5880,5182.8 5777.2,5182.8 5755,5205 5755,5405 6039.1,5689.1 6039.1,5738.4 6046.2,5745.5 6081.2,5745.5 6176.4,5840.6 6181.2,5840.6 6187.7,5847.1 6187.7,5851.9 LEVEL_SHIFFTER-1.2@6206.9,5871.2 ; v1(5950,5160) 5950,5200 5960,5210 5967.5,5210 5973.1,5215.6 5992.1,5215.6 6005.6,5202.1 6005.6,5174.4 6028,5152 v1(6091.3,5152)
  Bottom Layer w10: v1(5898,5150) 5940,5150 v1(5950,5160) ; v1(6091.3,5152) 6118,5152 6151.1,5118.9 U24.28@6151.1,5056
LED4: LED16.3 LEVEL_SHIFFTER-2.4 | length 1180.1
  Top Layer w10: v1(5905,5660.8) 5968.3,5660.8 5983.4,5676 5983.4,5857.3 6002,5875.9 LED16.3@6002,5896.7 ; LEVEL_SHIFFTER-2.4@5923.6,4935.6 5926.9,4939 5970.8,4939 5986.6,4954.8 5986.6,5188.6 v1(5982.6,5192.6)
  Bottom Layer w10: v1(5905,5660.8) 5893.9,5660.8 5845,5611.9 5845,5375 5982.6,5237.4 v1(5982.6,5192.6)
LED4-IN: LEVEL_SHIFFTER-2.2 U24.37 | length 308
  Top Layer w10: v1(5702.3,4985.7) 5702.3,4917.1 5719.9,4899.5 5742.5,4899.5 5816.6,4973.6 LEVEL_SHIFFTER-2.2@5830.8,4973.6
  Bottom Layer w10: v1(5702.3,4985.7) 5702.3,5056.2 U24.37@5704,5057.9
LED_RX: Bottom_PCB.11 CH340K.8 R-RX1.1 | length 3880.5
  Top Layer w10: v1(5154.4,3754.8) 5154.4,3793.1 5210.7,3849.4 5331.3,3849.4 5426.2,3754.5 5478.1,3754.5 5491.6,3767.9 5491.6,3780.6 5521.3,3810.3 5521.3,3821.9 5603.7,3904.4 5638.7,3904.4 v1(5772.7,4038.4) ; v1(5785.6,5285) 5785.6,5386.3 5928.7,5529.4 6005.7,5529.4 6021.7,5545.4 6021.7,5558.1 6043.4,5579.8 6074,5579.8 6120.4,5533.3 6120.4,5529.4 v1(6170.5,5479.3) ; R-RX1.1@5851.6,5212.5 5851.6,5216.6 R-RX1.1@5853.2,5218.2 ; v1(5875,5240) R-RX1.1@5853.2,5218.2 ; CH340K.8@5919.8,5316.4 5917.2,5319 5878.2,5319 5845.4,5286.1 5845.4,5226.1 R-RX1.1@5853.2,5218.2 ; v1(6041.1,4335.3) 6086,4380.2 6122.9,4380.2 6136.3,4393.7 6136.3,4412.8 6122.9,4426.2 6110.2,4426.2 6080.6,4455.7 v1(6080.6,4649.2) ; v1(6185.6,5212) 6185.6,5053.2 6205.8,5033.1 6205.8,5016.5 v1(6185.9,4996.6)
  Bottom Layer w10: v1(5154.4,3754.8) Bottom_PCB.11@5154.4,3824.3 ; v1(5772.7,4038.4) 5854.7,4120.3 5854.7,4201.2 5898.7,4245.2 5898.7,4284.3 5949.6,4335.3 v1(6041.1,4335.3) ; v1(5785.6,5285) 5785.6,5265.3 5782,5261.6 5782,5242.6 5785.6,5239 5785.6,5229.4 5805,5210 5845,5210 v1(5875,5240) ; v1(6080.6,4649.2) 6089.9,4658.5 6089.9,4911.7 6094.5,4916.4 6095.2,4916.4 6101.7,4922.9 6114.4,4922.9 6127.9,4936.4 6127.9,4963.6 6160.9,4996.6 v1(6185.9,4996.6) ; v1(6170.5,5479.3) 6133.4,5516.4 6090.8,5516.4 6060.6,5486.3 6060.6,5378 6115.1,5323.5 6115.1,5304.6 6185.6,5234 v1(6185.6,5212)
LED_TX: Bottom_PCB.10 CH340K.9 R-TX1.1 | length 3513.9
  Top Layer w10: v1(5193.7,3754.8) 5193.7,3776.8 5227,3810 5315,3810 5406.5,3718.5 5473.5,3718.5 5620,3865 5645,3865 v1(5800.6,4020.6) ; R-TX1.1@5805.7,5215.4 5805,5216.1 v1(5805,5252.1) 5825,5272.1 5825,5370 5945,5490 5986.1,5490 6035.7,5539.6 6035.7,5552.3 6049.2,5565.7 6068.2,5565.7 6104.1,5529.8 6104.1,5490 v1(6142.6,5451.5) ; v1(5872.3,5271.6) 5872.3,5273.9 v1@5879.4,5281 ; 5879.8,5281.2 5880.4,5280.6 CH340K.9@5918.2,5280.6 ; v1(6050,4290) 6050,4311.7 6104.5,4366.2 6128.7,4366.2 6150.3,4387.9 6150.3,4418.6 6094.6,4474.2 6094.6,4623.9 v1(6120,4649.2) ; v1(6211.4,4979.7) 6227,4995.3 6233.6,4995.3 6245.1,5006.8 6245.1,5049.4 6225,5069.6 v1(6225,5212)
  Bottom Layer w10: v1(5193.7,3754.8) Bottom_PCB.10@5193.7,3824.3 ; v1(5800.6,4020.6) 5894,4114 5894,4220.7 5912.7,4239.4 5912.7,4242.7 5960,4290 v1(6050,4290) ; v1(5805,5252.1) 5852.9,5252.1 v1(5872.3,5271.6) ; v1(6120,4649.2) 6120,4898.2 6201.5,4979.7 v1(6211.4,4979.7) ; v1(6142.6,5451.5) 6117.1,5477.1 6107.1,5477.1 6100,5470 6100,5375.3 6225,5250.3 v1(6225,5212)
MAC_CLK: PHY.14 R42.2 | length 155.9
  Top Layer w10: PHY.14@5108,5435.3 5108,5478 5135.9,5505.9 5135.9,5573.7 R42.2@5140.1,5577.9
MAC_CRS: PHY.11 R11.1 SBC.33 | length 799.2
  Top Layer w10: PHY.11@5155.1,5389.5 5178.2,5389.5 5180,5387.7 5190,5387.7 5258.2,5455.9 5258.2,5527.3 5274.6,5543.8 5291.3,5543.8 5311.3,5563.8 R11.1@5337.2,5563.8 5359,5541.9 v1(5361.9,5541.9) ; v1(5350,5460) 5350,5435.6 5349,5434.6 5349,5397 5390.4,5355.6 5422.7,5355.6 5449.5,5382.4 5449.5,5399.5 5470,5420 5470,5423.9 5476,5429.9 5476,5469.1 v1(5510,5503.1)
  Bottom Layer w10: v1(5350,5460) 5361.9,5471.9 v1(5361.9,5541.9) ; v1(5510,5503.1) SBC.33@5553,5503.1
MAC_MDC: PHY.13 SBC.30 | length 1258.8
  Top Layer w10: PHY.13@5129.2,5435.1 5140.2,5446.1 5154.8,5446.1 5183.8,5475.1 5183.8,5572.6 5205.4,5594.2 5259.3,5594.2 5260.8,5592.7 v1(5288.3,5592.7) ; v1(5406.6,5394.6) 5419.5,5407.5 5419.5,5420 5433.9,5434.4 5433.9,5473.6 5439.9,5479.6 5439.9,5591.4 5433.9,5597.4 5433.9,5772.4 5460.4,5798.9 5470.3,5798.9 v1(5485.9,5814.5)
  Bottom Layer w10: v1(5288.3,5592.7) 5413,5592.7 5444,5561.7 5444,5447.2 5419.5,5422.7 5419.5,5407.5 v1(5406.6,5394.6) ; SBC.30@5434.8,5700 5424.8,5700 5420.2,5704.6 5420.2,5740 5417.8,5742.4 5417.8,5756.3 5460.4,5798.9 5470.3,5798.9 v1(5485.9,5814.5)
MAC_MDIO: PHY.12 R41.1 SBC.31 | length 1459.3
  Top Layer w10: PHY.12@5155.1,5409.2 5166.1,5420.2 5166.1,5434.8 5199.8,5468.5 ; R41.1@5228.4,5480.5 5216.4,5468.5 5199.8,5468.5 ; v1(5271.9,5566.7) 5264.2,5566.7 5252.7,5578.2 5212.1,5578.2 5199.8,5566 5199.8,5468.5 ; v1(5388,5418.4) 5403.6,5434 5410.8,5434 5417.9,5441.1 5417.9,5480.2 5423.9,5486.2 5423.9,5584.8 5417.9,5590.8 5417.9,5779 5449.1,5810.2 5449.1,5820.1 v1(5464.7,5835.7)
  Bottom Layer w10: v1(5271.9,5566.7) 5294.8,5566.7 5304.8,5576.7 5406.3,5576.7 5428,5555 5428,5453.8 5408.2,5434 5403.6,5434 v1(5388,5418.4) ; v1(5464.7,5835.7) 5469.6,5830.7 5476.3,5837.5 5495.4,5837.5 5508.9,5824 5508.9,5804.9 5459.6,5755.7 5459.6,5642.6 5467.2,5635 5467.2,5624.6 5473.6,5618.1 5484.1,5618.1 5525,5577.2 5548.3,5577.2 SBC.31@5553,5581.9
MAC_RXD0: PHY.8 R10.2 R38.2 | length 190.2
  Top Layer w10: PHY.8@5155.1,5330.5 5158.3,5327.3 5222.6,5327.3 R38.2@5230.3,5335 5254.7,5335 5262.8,5343.1 5262.8,5356.6 5269.2,5363 5282.7,5363 R10.2@5310,5390.3
MAC_RXD1: PHY.7 R9.2 R37.2 | length 148.6
  Top Layer w10: PHY.7@5155.1,5310.8 5190.9,5274.9 R37.2@5231,5274.9 ; R9.2@5232.4,5214.4 R37.2@5232.4,5272.2
MAC_RXER: PHY.10 R12.1 SBC.32 | length 782.4
  Top Layer w10: PHY.10@5155.1,5369.8 5178.2,5369.8 5180,5371.7 5196.7,5371.7 5274.2,5449.2 5274.2,5520.7 5281.3,5527.8 5291.8,5527.8 5311.9,5507.8 R12.1@5337.7,5507.8 5348.6,5507.8 5390,5466.4 5390,5452.9 5365,5428 5365,5403.6 5397.1,5371.6 5416.1,5371.6 5429.6,5385.1 5429.6,5397.8 5433.5,5401.7 5433.5,5414.2 5435.3,5416 5439.5,5416 5460,5436.5 5460,5530 5470,5540 5507.5,5540 v1(5510,5542.5)
  Bottom Layer w10: v1(5510,5542.5) SBC.32@5553,5542.5
MAC_TXD0: PHY.17 R40.2 | length 156.6
  Top Layer w10: R40.2@5011.2,5572.2 5011.2,5483.3 5035.4,5459.2 5040.9,5459.2 5047.3,5452.7 5047.3,5447.2 5050.5,5444.1 PHY.17@5050.5,5435.1
MAC_TXD1: PHY.18 R39.2 | length 209.2
  Top Layer w10: R39.2@4948.5,5608.3 4948.5,5570.2 4960.2,5558.4 4963.5,5558.4 4975.7,5546.2 4975.7,5496.2 5030.8,5441.1 PHY.18@5030.8,5435.1
MAC_TXEN: PHY.16 SBC.34 | length 837
  Top Layer w10: v1(5046.1,5495.8) 5070.2,5471.7 PHY.16@5070.2,5435.1 ; v1(5483.1,5373.7) 5569.6,5460.2 v1(5620.5,5460.2)
  Bottom Layer w10: v1(5046.1,5495.8) 5175.2,5495.8 5217.8,5538.4 5236.9,5538.4 5365,5410.3 5365,5403.6 5397.1,5371.6 5416.1,5371.6 5418.2,5373.7 v1(5483.1,5373.7) ; SBC.34@5558,5465.3 5563.1,5460.2 v1(5620.5,5460.2)
MASKROM: SBC.43
MASKROM_BTN: Bottom_PCB.6 MASKROM.2 Q5.1 R23.1 | length 2412.7
  Top Layer w10: Q5.1@3979.7,4442.6 3918.7,4381.6 MASKROM.2@3918.7,4315 3945,4315 R23.1@3984.6,4275.4
  Bottom Layer w10: v1(3927.1,4396.4) 3927.1,3863.6 4131.6,3659 5291.2,3659 5353.2,3721 Bottom_PCB.6@5353.2,3829.2
MIC1: R59.2 Top_PCB.10 | length 248.8
  Top Layer w10: R59.2@6695,5724.7 6724.7,5724.7 v1(6735,5735)
  Bottom Layer w10: v1(6735,5735) 6760,5760 6760,5830 6767.1,5837.1 6853,5837.1 Top_PCB.10@6855.3,5839.4
MIC2: R58.2 Top_PCB.9 | length 4070.3
  Top Layer w10: v1(4840,4375.5) 4857,4358.5 4857,4285 4886,4256 5214,4256 5240,4230 5345,4230 v1(5365,4210) ; v1(5345.3,4465.3) 5362.2,4465.3 R58.2@5381.5,4445.9 ; v1(5425,4135) 5478.8,4135 5486.3,4142.5 5572.2,4142.5 5579.7,4135 v1(5610,4135) ; v1(5790,4540) 5790,4420 v1(5810,4400) ; v1(6050,4860) 6060,4860 6156.7,4956.7 6220.9,4956.7 6234.4,4970.2 6234.4,4976.3 6298.1,5040 6462.8,5040 v1(6463.7,5039.1) ; v1(6625,5300) 6643.8,5318.8 6643.8,5379.1 6635.8,5387 6635.8,5431.6 6643.8,5439.5 v1(6643.8,5475.1)
  Bottom Layer w10: v1(4840,4375.5) 4840,4390 4872.2,4422.2 4976.7,4422.2 5019.3,4379.6 5289.6,4379.6 5345.3,4435.3 v1(5345.3,4465.3) ; v1(5365,4210) 5425,4150 v1(5425,4135) ; v1(5610,4135) 5709.8,4135 5794,4219.2 5794,4384 v1(5810,4400) ; v1(5790,4540) 5810,4560 5810,4730 5940,4860 v1(6050,4860) ; v1(6463.7,5039.1) 6473.6,5048.9 6473.6,5157.1 6616.4,5300 v1(6625,5300) ; v1(6643.8,5475.1) 6734.9,5566.2 6734.9,5702.4 6758,5725.5 6758,5738.2 6819.8,5800 Top_PCB.9@6855.3,5800
MIC3: R57.2 Top_PCB.8 | length 2768.2
  Top Layer w10: v1(5333,4507.4) R57.2@5373.8,4507.4 ; v1@5500,4886.7 5504.6,4882.1 5733.6,4882.1 5793.5,4822.3 v1(5793.5,4816.1) ; v1(6049.6,4822.6) 6092.8,4822.6 6209.2,4939 6246.7,4939 v1(6291.3,4983.6) ; v1@6364.7,5128 6397.6,5095.1 6447,5095.1 ; 6447,5095.8 6500.2,5149.1 v1(6500.9,5149.1) ; v1@6671.3,5447.1 6673.4,5447.1 6678,5442.4 6709,5442.4 6722.4,5429 6722.4,5409.9 6717.3,5404.8 6717.3,5393.1 6695,5370.8 v1(6695,5317.6)
  Bottom Layer w10: v1(5333,4507.4) 5408,4507.4 5438.3,4537.6 5438.3,4560.4 5466,4588.1 5467.7,4588.1 5502.4,4622.8 5504.7,4881 v1(5496.2,4889.6) ; v1(5793.5,4816.1) 5856.1,4816.1 5923,4883 6059.5,4883 6073,4869.5 6073,4850.5 6049.6,4827.1 v1(6049.6,4822.6) ; v1@6293.9,4986.2 6312.7,4986.2 6350.5,5023.9 ; 6350.5,5025.7 6367.5,5042.7 6367.5,5076.1 6364.9,5078.7 v1(6364.9,5131.4) ; v1(6500.9,5149.1) 6526.4,5149.1 v1(6695,5317.6) ; v1(6671.6,5447.3) 6774.2,5549.9 6774.2,5730.5 6804.4,5760.6 Top_PCB.8@6855.3,5760.6
MIC4: R56.2 Top_PCB.7 | length 4781.7
  Top Layer w10: v1(5026.5,4413.2) 5017.5,4422.2 4957.6,4422.2 4934,4398.6 4921.3,4398.6 4911.3,4388.6 4911.3,4356.1 4926.4,4340.9 5469.1,4340.9 5483.8,4326.2 v1(5483.8,4309) ; v1(5344.4,4551.4) 5367.4,4551.4 R56.2@5383.8,4567.9 ; v1@5429.1,4041.4 5544.8,4041.4 v1@5552.7,4049.3 ; v1@5533.2,4198 5532.8,4198 v1@5535.2,4200.4 ; v1@5538.6,4200.4 v1(5539.4,4200.4) ; v1@5538.6,4201.6 5547.8,4210.8 v1@5547.8,4275.7 ; v1(5802.9,4108.6) 5806.3,4112 5995.8,4112 6036.6,4071.2 v1(6036.6,4035.7)
  Bottom Layer w10: v1@5016.6,4419.7 5034.8,4401.5 5277.3,4401.5 5283.4,4407.6 5288.4,4407.6 5312.1,4431.3 5312.1,4495.7 5310,4497.8 5310,4517.1 v1(5344.4,4551.4) ; v1(5427.1,4045.8) 5427.1,4104.6 5448,4125.5 5464.4,4125.5 v1(5539.4,4200.4) ; v1@5485.9,4306.8 5578.8,4306.8 5595.5,4290.1 5595.5,4280.1 5588.4,4273.1 5578.4,4273.1 5575.4,4276.1 v1(5550.8,4276.1) ; v1(5553.7,4046.9) 5741.2,4046.9 v1(5802.9,4108.6) ; v1(6036.6,4035.7) 6056.7,4015.7 6122.7,4015.7 6249.3,4142.2 6309.2,4142.2 6390,4223 6390,4261.5 ; 6390,4262.2 6390,4648.6 6494.1,4752.7 ; 6493.9,4753 6521.5,4780.6 6521.5,5098.4 6708,5284.9 6767.2,5284.9 6832.6,5350.3 6832.6,5389.9 6806.7,5415.8 v1@6701.9,5415.8 ; v1(6699.4,5419.4) 6813.6,5533.6 6813.6,5714.2 6820.7,5721.3 Top_PCB.7@6855.3,5721.3
MOD_D+: R47.2 USB_SWITCH.7 | length 443.5
  Top Layer w10: R47.2@4334.7,5035 4359.2,5010.5 4375.8,5010.5 4400,4986.3 4400,4880 4480,4800 4495,4800 4502,4807 4528,4807 4559.9,4775.1 USB_SWITCH.7@4602.5,4775.1
MOD_D-: R46.2 USB_SWITCH.6 | length 518.5
  Top Layer w10: R46.2@4334.7,4970 4344.7,4980 4366.2,4980 4376.2,4970 4376.2,4871.1 4463.4,4784 4495,4784 4502,4777 v1(4524,4777) ; USB_SWITCH.6@4602.5,4800.1 4602.6,4800 v1(4650,4800)
  Bottom Layer w10: v1(4524,4777) 4527,4777 4550,4800 v1(4650,4800)
NIC_RX+: FILT.6 PHY.23 R3.2 | length 1435
  Top Layer w10: FILT.6@4555.5,6120 4607.7,6120 4649.7,6162 4659.7,6162 4666.8,6154.9 4666.8,5960.6 4819,5808.4 4819,5578.4 4838.7,5558.7 4838.7,5548.8 v1(4843,5544.5) ; R3.2@4652.4,5452.2 4652.4,5485.8 v1(4683.9,5517.3) ; v1(4897.5,5317.5) 4957.5,5317.5 4970.5,5330.5 PHY.23@5004.9,5330.5
  Bottom Layer w10: v1(4683.9,5517.3) 4709.7,5543.1 v1@4842.1,5543.1 ; v1(4843,5544.5) 4869.8,5517.7 4879.7,5517.7 4886.8,5510.6 4886.8,5391.6 4881,5385.9 4881,5334 v1(4897.5,5317.5)
NIC_RX-: C27.2 FILT.2 FILT.7 FILT.8 PHY.22 R4.2 R36.1 | length 2301.9
  Top Layer w10: R36.1@4111.3,5813.6 4381.8,5813.6 4495.2,5927 4502.2,5920 FILT.2@4555.5,5920 4557.5,5918 v1(4614.8,5918) ; 4494.7,5927 4494.7,6158.9 4505.4,6169.6 4554.4,6169.6 FILT.7@4556.6,6167.5 ; FILT.7@4555.5,6170.1 FILT.8@4555.5,6220 4607.7,6220 4649.7,6178 4666.3,6178 4682.8,6161.6 4682.8,5967.2 4835,5815 4835,5585 4850,5570 4859.9,5570 v1(4867.5,5562.4) 4912.3,5562.4 R4.2@4949.7,5524.9 ; v1(4636.6,5865.7) 4636.6,5813.5 C27.2@4643,5807.1 ; v1(4935.6,5342.9) 4942.9,5350.2 PHY.22@5004.9,5350.2
  Bottom Layer w10: v1(4614.8,5918) 4636.6,5896.2 v1(4636.6,5865.7) ; v1(4867.5,5562.4) 4886.2,5543.7 4886.2,5533.8 4902.8,5517.2 4902.8,5385 4897,5379.2 4897,5350.5 4907.5,5340 4932.7,5340 v1(4935.6,5342.9)
NIC_TX+: FILT.1 PHY.21 R6.1 | length 964.4
  Top Layer w10: FILT.1@4555.5,5870 4607.7,5870 4649.7,5912 4659.7,5912 4760,5811.7 4760,5503.1 4872,5391.1 4872,5389.9 4878.4,5383.5 4879.6,5383.5 4889.9,5373.2 4906.5,5373.2 4910,5369.7 v1(4920,5369.7) 4920.1,5369.8 PHY.21@5004.9,5369.8 ; R6.1@4772,5367.6 4791.4,5367.6 4842.4,5418.5
NIC_TX-: FILT.3 PHY.20 R5.1 | length 901.6
  Top Layer w10: FILT.3@4555.5,5970 4607.7,5970 4649.7,5928 4666.3,5928 4782.3,5812.1 4782.3,5503.4 4895.8,5390 ; 4896.5,5389.2 4906.5,5389.2 4910,5392.7 4920.1,5392.7 ; R5.1@4909.1,5417.3 4909.1,5403.8 4920.1,5392.7 ; PHY.20@5004.9,5389.5 5001.7,5392.7 4920.1,5392.7
PHONE_DET: Bottom_PCB.7 SBC.82 | length 1261.1
  Top Layer w10: v1(4602.2,4215.8) 4602.2,4195.5 4603.2,4194.5 4603.2,4162.5 4602.2,4161.5 4602.2,3984.7 4857,3729.9 v1(5306.8,3729.9)
  Bottom Layer w10: v1(4602.2,4215.8) 4614.7,4228.3 SBC.82@4614.7,4324.9 ; v1(5306.8,3729.9) 5306.8,3832 Bottom_PCB.7@5308.7,3833.9
PHONE_L: Bottom_PCB.9 SBC.80 | length 1288.3
  Top Layer w10: v1@4702,4238.8 4741,4238.8 4746.8,4233 4768.7,4233 v1(4783.7,4218) ; v1(5003.7,4210) 5022.3,4191.4 5217,4191.4 v1(5227.7,4202.2) 5228.4,4201.5 v1(5318.5,4201.5)
  Bottom Layer w10: SBC.80@4688.3,4321.7 4688.3,4248.8 v1@4697.6,4239.5 ; v1(4783.7,4218) 4882.6,4119.1 4912.2,4119.1 4918.2,4125.2 4932.8,4125.2 4946.3,4138.6 4946.3,4153.3 4970,4177 4970.7,4177 v1(5003.7,4210) ; Bottom_PCB.9@5233.1,3817 5233.1,3883.6 5388,4038.6 5388,4130.9 5318.5,4200.5 v1(5318.5,4201.5)
  other v1: 4698.1,4238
